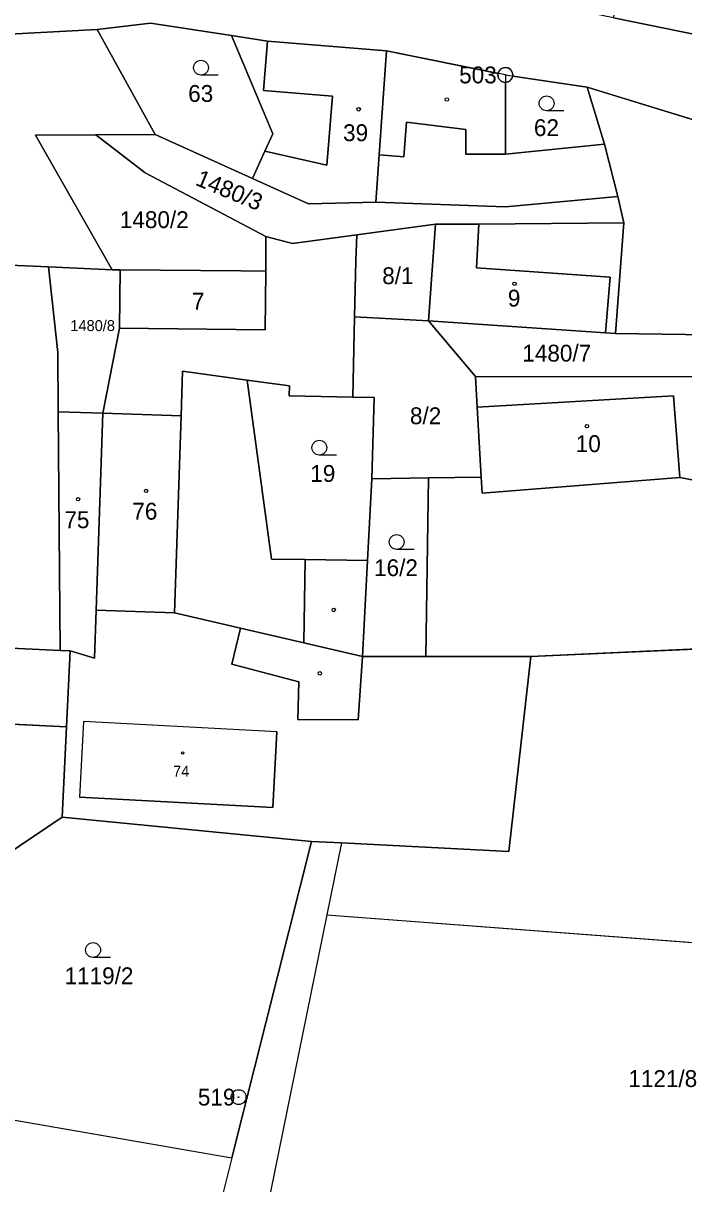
# Model space of a CAD drawing. Extents: x -760642 to -757221, y -1092371 to -1088855.
# Drawn here: x -759196.6 to -759130, y -1089899.5 to -1089782.4 of the extents above; entities that cross this region are included whole.
import ezdxf

# ---------------------------------------------------------------- set-up
doc = ezdxf.new("R2010")
doc.units = 0
for name, color, linetype in [('Vrstva 1', 7, 'Continuous'), ('Vrstva 17', 7, 'Continuous'), ('Vrstva 18', 7, 'Continuous'), ('Vrstva 19', 7, 'Continuous'), ('Vrstva 24', 7, 'Continuous'), ('Vrstva 25', 7, 'Continuous'), ('Vrstva 26', 7, 'Continuous'), ('Vrstva 27', 7, 'Continuous'), ('Vrstva 4', 7, 'Continuous')]:
    doc.layers.add(name, color=color, linetype=linetype)

msp = doc.modelspace()

# ---------------------------------------------------------------- linework, layer by layer
at = {"layer": 'Vrstva 1'}
for p, q in [((-759183.79, -1089782.45), (-759189.17, -1089783.09)), ((-759175.61, -1089783.69), (-759183.79, -1089782.45)), ((-759137.06, -1089781.89), (-759125.03, -1089784.34)), ((-759189.17, -1089783.09), (-759251.73, -1089786.4)), ((-759189.17, -1089783.09), (-759183.33, -1089793.67)), ((-759171.98, -1089784.24), (-759175.61, -1089783.69)), ((-759171.46, -1089793.61), (-759175.61, -1089783.69)), ((-759171.98, -1089784.24), (-759159.99, -1089785.24)), ((-759147.98, -1089787.66), (-759159.99, -1089785.24)), ((-759147.98, -1089787.66), (-759147.97, -1089795.66)), ((-759147.98, -1089787.66), (-759139.72, -1089788.89)), ((-759107.66, -1089798.75), (-759139.72, -1089788.89)), ((-759137.98, -1089794.63), (-759139.72, -1089788.89)), ((-759195.39, -1089793.75), (-759189.3, -1089793.71)), ((-759187.67, -1089807.31), (-759195.39, -1089793.75)), ((-759189.3, -1089793.71), (-759183.33, -1089793.67)), ((-759184.34, -1089797.55), (-759189.3, -1089793.71)), ((-759173.49, -1089798.11), (-759183.33, -1089793.67)), ((-759171.46, -1089793.61), (-759172.25, -1089795.35)), ((-759172.25, -1089795.35), (-759173.49, -1089798.11)), ((-759147.97, -1089795.66), (-759137.98, -1089794.63)), ((-759136.64, -1089799.91), (-759137.98, -1089794.63)), ((-759172.14, -1089803.96), (-759184.34, -1089797.55)), ((-759167.84, -1089800.66), (-759173.49, -1089798.11)), ((-759147.96, -1089800.96), (-759136.64, -1089799.91)), ((-759136.64, -1089799.91), (-759136.01, -1089802.59)), ((-759167.84, -1089800.66), (-759161.04, -1089800.5)), ((-759161.04, -1089800.5), (-759147.96, -1089800.96)), ((-759150.67, -1089802.72), (-759136.01, -1089802.59)), ((-759136.01, -1089802.59), (-759136.87, -1089813.75)), ((-759162.97, -1089803.79), (-759169.48, -1089804.68)), ((-759163.06, -1089806.39), (-759162.97, -1089803.79)), ((-759162.97, -1089803.79), (-759155.04, -1089802.71)), ((-759155.73, -1089812.48), (-759155.04, -1089802.71)), ((-759155.04, -1089802.71), (-759150.67, -1089802.72)), ((-759172.17, -1089807.46), (-759172.14, -1089803.96)), ((-759172.14, -1089803.96), (-759169.48, -1089804.68)), ((-759197.98, -1089806.87), (-759194.09, -1089807.03)), ((-759194.09, -1089807.03), (-759187.67, -1089807.31)), ((-759193.16, -1089815.67), (-759194.09, -1089807.03)), ((-759186.87, -1089807.32), (-759187.67, -1089807.31)), ((-759186.93, -1089813.22), (-759186.87, -1089807.32)), ((-759186.87, -1089807.32), (-759174.67, -1089807.44)), ((-759163.06, -1089806.39), (-759163.2, -1089812.06)), ((-759174.67, -1089807.44), (-759172.17, -1089807.46)), ((-759163.2, -1089812.06), (-759163.39, -1089820.18)), ((-759163.2, -1089812.06), (-759155.73, -1089812.48)), ((-759155.73, -1089812.48), (-759151, -1089818.09)), ((-759137.87, -1089813.68), (-759155.73, -1089812.48)), ((-759186.93, -1089813.22), (-759188.62, -1089821.79)), ((-759136.87, -1089813.75), (-759137.87, -1089813.68)), ((-759136.87, -1089813.75), (-759127.46, -1089813.87)), ((-759193.11, -1089821.64), (-759193.16, -1089815.67)), ((-759180.55, -1089817.55), (-759180.7, -1089822.05)), ((-759180.55, -1089817.55), (-759174.04, -1089818.45)), ((-759174.04, -1089818.45), (-759169.77, -1089819.04)), ((-759171.58, -1089836.5), (-759174.04, -1089818.45)), ((-759169.77, -1089819.04), (-759169.79, -1089820.05)), ((-759151, -1089818.09), (-759127.99, -1089818.13)), ((-759150.82, -1089821.19), (-759151, -1089818.09)), ((-759169.79, -1089820.05), (-759163.39, -1089820.18)), ((-759163.39, -1089820.18), (-759161.23, -1089820.22)), ((-759161.23, -1089820.22), (-759161.47, -1089828.41)), ((-759150.41, -1089828.24), (-759150.82, -1089821.19)), ((-759192.9, -1089845.73), (-759193.11, -1089821.64)), ((-759188.62, -1089821.79), (-759193.11, -1089821.64)), ((-759188.62, -1089821.79), (-759189.28, -1089841.67)), ((-759180.7, -1089822.05), (-759188.62, -1089821.79)), ((-759161.47, -1089828.41), (-759161.9, -1089836.65)), ((-759155.73, -1089828.32), (-759161.47, -1089828.41)), ((-759156, -1089846.35), (-759155.73, -1089828.32)), ((-759150.41, -1089828.24), (-759155.73, -1089828.32)), ((-759150.32, -1089829.84), (-759150.41, -1089828.24)), ((-759150.32, -1089829.84), (-759130.36, -1089828.26)), ((-759125.67, -1089829.2), (-759130.36, -1089828.26)), ((-759168.18, -1089836.55), (-759171.58, -1089836.5)), ((-759161.9, -1089836.65), (-759168.18, -1089836.55)), ((-759161.9, -1089836.65), (-759162.4, -1089846.35)), ((-759189.28, -1089841.67), (-759189.44, -1089846.51)), ((-759181.36, -1089841.93), (-759189.28, -1089841.67)), ((-759174.72, -1089843.48), (-759181.36, -1089841.93)), ((-759168.31, -1089844.97), (-759174.72, -1089843.48)), ((-759145.4, -1089846.35), (-759093.49, -1089843.95)), ((-759192.9, -1089845.73), (-759191.9, -1089845.78)), ((-759192.26, -1089853.42), (-759191.9, -1089845.78)), ((-759191.9, -1089845.78), (-759189.44, -1089846.51)), ((-759162.4, -1089846.35), (-759168.31, -1089844.97)), ((-759162.4, -1089846.35), (-759156, -1089846.35)), ((-759156, -1089846.35), (-759145.4, -1089846.35)), ((-759145.4, -1089846.35), (-759147.63, -1089866.02)), ((-759206.56, -1089852.74), (-759192.26, -1089853.42)), ((-759192.7, -1089862.53), (-759192.26, -1089853.42)), ((-759192.7, -1089862.53), (-759210.19, -1089874.31)), ((-759192.7, -1089862.53), (-759167.54, -1089864.99)), ((-759167.54, -1089864.99), (-759175.58, -1089896.9)), ((-759164.51, -1089865.15), (-759167.54, -1089864.99)), ((-759164.51, -1089865.15), (-759165.99, -1089872.4)), ((-759147.63, -1089866.02), (-759164.51, -1089865.15)), ((-759165.99, -1089872.4), (-759173.44, -1089908.9)), ((-759165.99, -1089872.4), (-759090.65, -1089878.08)), ((-759210.46, -1089890.87), (-759175.58, -1089896.9)), ((-759175.58, -1089896.9), (-759181.66, -1089921.05))]:
    msp.add_line(p, q, dxfattribs=at)
at = {"layer": 'Vrstva 24'}
for centre, radius in [((-759147.98, -1089787.66), 0.75), ((-759147.98, -1089787.66), 0.0327), ((-759174.91, -1089890.79), 0.75), ((-759174.91, -1089890.79), 0.0327)]:
    msp.add_circle(centre, radius, dxfattribs=at)
at = {"layer": 'Vrstva 25'}
for p, q in [((-759176.95, -1089787.68), (-759178.7, -1089787.68)), ((-759142.07, -1089791.28), (-759143.82, -1089791.28)), ((-759165.01, -1089826.02), (-759166.76, -1089826.02)), ((-759157.2, -1089835.53), (-759158.95, -1089835.53)), ((-759187.84, -1089876.7), (-759189.59, -1089876.7))]:
    msp.add_line(p, q, dxfattribs=at)
for centre, radius in [((-759178.7, -1089786.93), 0.75), ((-759143.82, -1089790.53), 0.75), ((-759162.78, -1089791.13), 0.175), ((-759153.89, -1089790.14), 0.175), ((-759147.06, -1089808.73), 0.175), ((-759139.75, -1089823.1), 0.175), ((-759166.76, -1089825.27), 0.75), ((-759184.24, -1089829.63), 0.175), ((-759191.1, -1089830.47), 0.175), ((-759158.95, -1089834.78), 0.75), ((-759165.3, -1089841.64), 0.175), ((-759166.7, -1089848.03), 0.175), ((-759180.55, -1089856.07), 0.117), ((-759189.59, -1089875.95), 0.75)]:
    msp.add_circle(centre, radius, dxfattribs=at)
at = {"layer": 'Vrstva 26'}
for points in [[(-759118.09, -1089757.67), (-759131.06, -1089758.08), (-759131.4, -1089747.57), (-759150.38, -1089748.18), (-759150.32, -1089753.17), (-759145.12, -1089753.12), (-759145.07, -1089757.83), (-759142.7, -1089757.82), (-759142.69, -1089760.22), (-759137.99, -1089760.2), (-759136.17, -1089771.28), (-759137.06, -1089781.89), (-759125.03, -1089784.34), (-759123.91, -1089784.65), (-759122.05, -1089777.39), (-759116.22, -1089778.89), (-759116.87, -1089757.63), (-759118.09, -1089757.67)], [(-759091.045, -1089805.166), (-759071.27, -1089811.68), (-759049.32, -1089817.46), (-759042.71, -1089818.15), (-759029.2, -1089819.24), (-759029.34, -1089815.45), (-759032.5, -1089809.35), (-759051.44, -1089805), (-759059.96, -1089803.05), (-759085.48, -1089798.88), (-759102.96, -1089790.95), (-759107.14, -1089789.05), (-759108.48, -1089788.44), (-759123.91, -1089784.65), (-759125.03, -1089784.34), (-759137.06, -1089781.89), (-759146.495, -1089779.96)], [(-759313.165, -1089810.283), (-759304.6, -1089803.62), (-759296.53, -1089798.79), (-759284.76, -1089793.72), (-759267.64, -1089788.76), (-759251.73, -1089786.4), (-759189.17, -1089783.09), (-759183.79, -1089782.45), (-759175.61, -1089783.69), (-759171.98, -1089784.24), (-759159.99, -1089785.24), (-759148.715, -1089787.512)], [(-759172.25, -1089795.35), (-759171.46, -1089793.61), (-759175.61, -1089783.69), (-759183.79, -1089782.45), (-759189.17, -1089783.09), (-759183.33, -1089793.67), (-759173.49, -1089798.11), (-759172.25, -1089795.35)], [(-759195.39, -1089793.75), (-759189.3, -1089793.71), (-759183.33, -1089793.67), (-759189.17, -1089783.09), (-759251.73, -1089786.4), (-759267.64, -1089788.76), (-759284.76, -1089793.72)], [(-759172.4, -1089789.22), (-759171.98, -1089784.24), (-759175.61, -1089783.69), (-759171.46, -1089793.61), (-759172.25, -1089795.35), (-759166, -1089796.78), (-759165.42, -1089789.81), (-759172.4, -1089789.22)], [(-759166, -1089796.78), (-759172.25, -1089795.35), (-759173.49, -1089798.11), (-759167.84, -1089800.66), (-759161.04, -1089800.5), (-759160.71, -1089795.73), (-759159.99, -1089785.24), (-759171.98, -1089784.24), (-759172.4, -1089789.22), (-759165.42, -1089789.81), (-759166, -1089796.78)], [(-759148.715, -1089787.512), (-759159.99, -1089785.24), (-759160.71, -1089795.73), (-759158.22, -1089795.91), (-759157.96, -1089792.42), (-759151.97, -1089793.17), (-759151.97, -1089795.66), (-759147.97, -1089795.66), (-759147.979, -1089788.41)], [(-759147.979, -1089788.41), (-759147.97, -1089795.66), (-759137.98, -1089794.63), (-759139.72, -1089788.89), (-759147.238, -1089787.77)], [(-759147.238, -1089787.77), (-759139.72, -1089788.89), (-759107.66, -1089798.75), (-759091.986, -1089804.829)], [(-759091.986, -1089804.829), (-759107.66, -1089798.75), (-759139.72, -1089788.89), (-759137.98, -1089794.63), (-759136.64, -1089799.91), (-759136.01, -1089802.59), (-759136.87, -1089813.75), (-759127.46, -1089813.87), (-759127.24, -1089813.87), (-759124.98, -1089801.03), (-759108.39, -1089804.66), (-759104.51, -1089813.82), (-759099.17, -1089811.94), (-759081.2, -1089811.04), (-759049.32, -1089817.46), (-759071.27, -1089811.68), (-759091.045, -1089805.166)], [(-759151.97, -1089795.66), (-759151.97, -1089793.17), (-759157.96, -1089792.42), (-759158.22, -1089795.91), (-759160.71, -1089795.73), (-759161.04, -1089800.5), (-759147.96, -1089800.96), (-759136.64, -1089799.91), (-759137.98, -1089794.63), (-759147.97, -1089795.66), (-759151.97, -1089795.66)], [(-759197.98, -1089806.87), (-759194.09, -1089807.03), (-759187.67, -1089807.31), (-759195.39, -1089793.75)], [(-759186.87, -1089807.32), (-759174.67, -1089807.44), (-759172.17, -1089807.46), (-759172.14, -1089803.96), (-759184.34, -1089797.55), (-759189.3, -1089793.71), (-759195.39, -1089793.75), (-759187.67, -1089807.31), (-759186.87, -1089807.32)], [(-759189.3, -1089793.71), (-759184.34, -1089797.55), (-759172.14, -1089803.96), (-759169.48, -1089804.68), (-759162.97, -1089803.79), (-759155.04, -1089802.71), (-759150.67, -1089802.72), (-759136.01, -1089802.59), (-759136.64, -1089799.91), (-759147.96, -1089800.96), (-759161.04, -1089800.5), (-759167.84, -1089800.66), (-759173.49, -1089798.11), (-759183.33, -1089793.67), (-759189.3, -1089793.71)], [(-759137.4, -1089808.08), (-759137.87, -1089813.68), (-759136.87, -1089813.75), (-759136.01, -1089802.59), (-759150.67, -1089802.72), (-759150.88, -1089807.11), (-759137.4, -1089808.08)], [(-759172.17, -1089807.46), (-759172.23, -1089813.37), (-759186.93, -1089813.22), (-759188.62, -1089821.79), (-759180.7, -1089822.05), (-759180.55, -1089817.55), (-759174.04, -1089818.45), (-759169.77, -1089819.04), (-759169.79, -1089820.05), (-759163.39, -1089820.18), (-759163.2, -1089812.06), (-759163.06, -1089806.39), (-759162.97, -1089803.79), (-759169.48, -1089804.68), (-759172.14, -1089803.96), (-759172.17, -1089807.46)], [(-759155.04, -1089802.71), (-759162.97, -1089803.79), (-759163.06, -1089806.39), (-759163.2, -1089812.06), (-759155.73, -1089812.48), (-759155.04, -1089802.71)], [(-759137.4, -1089808.08), (-759150.88, -1089807.11), (-759150.67, -1089802.72), (-759155.04, -1089802.71), (-759155.73, -1089812.48), (-759137.87, -1089813.68), (-759137.4, -1089808.08)], [(-759198.34, -1089806.85), (-759198.58, -1089814.41), (-759214.17, -1089813.83), (-759214.93, -1089832.99), (-759211.28, -1089833.14), (-759211.34, -1089844.86), (-759192.9, -1089845.73), (-759193.11, -1089821.64), (-759193.16, -1089815.67), (-759194.09, -1089807.03), (-759197.98, -1089806.87), (-759198.34, -1089806.85)], [(-759186.87, -1089807.32), (-759187.67, -1089807.31), (-759194.09, -1089807.03), (-759193.16, -1089815.67), (-759193.11, -1089821.64), (-759188.62, -1089821.79), (-759186.93, -1089813.22), (-759186.87, -1089807.32)], [(-759172.23, -1089813.37), (-759172.17, -1089807.46), (-759174.67, -1089807.44), (-759186.87, -1089807.32), (-759186.93, -1089813.22), (-759172.23, -1089813.37)], [(-759155.73, -1089812.48), (-759163.2, -1089812.06), (-759163.39, -1089820.18), (-759161.23, -1089820.22), (-759161.47, -1089828.41), (-759155.73, -1089828.32), (-759150.41, -1089828.24), (-759150.82, -1089821.19), (-759151, -1089818.09), (-759155.73, -1089812.48)], [(-759151, -1089818.09), (-759127.99, -1089818.13), (-759127.24, -1089813.87), (-759127.46, -1089813.87), (-759136.87, -1089813.75), (-759137.87, -1089813.68), (-759155.73, -1089812.48), (-759151, -1089818.09)], [(-759168.31, -1089844.97), (-759168.18, -1089836.55), (-759171.58, -1089836.5), (-759174.04, -1089818.45), (-759180.55, -1089817.55), (-759180.7, -1089822.05), (-759181.36, -1089841.93), (-759174.72, -1089843.48), (-759168.31, -1089844.97)], [(-759168.18, -1089836.55), (-759161.9, -1089836.65), (-759161.47, -1089828.41), (-759161.23, -1089820.22), (-759163.39, -1089820.18), (-759169.79, -1089820.05), (-759169.77, -1089819.04), (-759174.04, -1089818.45), (-759171.58, -1089836.5), (-759168.18, -1089836.55)], [(-759131.01, -1089820.04), (-759130.36, -1089828.26), (-759125.67, -1089829.2), (-759119.77, -1089828.99), (-759119.79, -1089820.53), (-759125.66, -1089818.71), (-759127.99, -1089818.13), (-759151, -1089818.09), (-759150.82, -1089821.19), (-759131.01, -1089820.04)], [(-759150.82, -1089821.19), (-759150.41, -1089828.24), (-759150.32, -1089829.84), (-759130.36, -1089828.26), (-759131.01, -1089820.04), (-759150.82, -1089821.19)], [(-759189.44, -1089846.51), (-759189.28, -1089841.67), (-759188.62, -1089821.79), (-759193.11, -1089821.64), (-759192.9, -1089845.73), (-759191.9, -1089845.78), (-759189.44, -1089846.51)], [(-759188.62, -1089821.79), (-759189.28, -1089841.67), (-759181.36, -1089841.93), (-759180.7, -1089822.05), (-759188.62, -1089821.79)], [(-759156, -1089846.35), (-759155.73, -1089828.32), (-759161.47, -1089828.41), (-759161.9, -1089836.65), (-759162.4, -1089846.35), (-759156, -1089846.35)], [(-759111.03, -1089828.68), (-759119.77, -1089828.99), (-759125.67, -1089829.2), (-759130.36, -1089828.26), (-759150.32, -1089829.84), (-759150.41, -1089828.24), (-759155.73, -1089828.32), (-759156, -1089846.35), (-759145.4, -1089846.35), (-759093.49, -1089843.95), (-759096.14, -1089828.16), (-759111.03, -1089828.68)], [(-759168.31, -1089844.97), (-759162.4, -1089846.35), (-759161.9, -1089836.65), (-759168.18, -1089836.55), (-759168.31, -1089844.97)], [(-759191.9, -1089845.78), (-759192.26, -1089853.42), (-759192.7, -1089862.53), (-759167.54, -1089864.99), (-759164.51, -1089865.15), (-759147.63, -1089866.02), (-759145.4, -1089846.35), (-759156, -1089846.35), (-759162.4, -1089846.35), (-759162.84, -1089852.71), (-759168.92, -1089852.68), (-759168.82, -1089848.88), (-759175.57, -1089847.1), (-759174.72, -1089843.48), (-759181.36, -1089841.93), (-759189.28, -1089841.67), (-759189.44, -1089846.51), (-759191.9, -1089845.78)], [(-759174.72, -1089843.48), (-759175.57, -1089847.1), (-759168.82, -1089848.88), (-759168.92, -1089852.68), (-759162.84, -1089852.71), (-759162.4, -1089846.35), (-759168.31, -1089844.97), (-759174.72, -1089843.48)], [(-759211.34, -1089844.86), (-759215.04, -1089844.69), (-759215.71, -1089852.31), (-759208.57, -1089852.65), (-759206.56, -1089852.74), (-759192.26, -1089853.42), (-759191.9, -1089845.78), (-759192.9, -1089845.73), (-759211.34, -1089844.86)], [(-759093.49, -1089843.95), (-759145.4, -1089846.35), (-759147.63, -1089866.02), (-759164.51, -1089865.15), (-759165.99, -1089872.4), (-759090.65, -1089878.08), (-759093.49, -1089843.95)], [(-759192.7, -1089862.53), (-759192.26, -1089853.42), (-759206.56, -1089852.74), (-759208.57, -1089852.65), (-759209, -1089858.46), (-759209.83, -1089870.65), (-759210.19, -1089874.31), (-759192.7, -1089862.53)], [(-759171.04, -1089853.93), (-759190.57, -1089852.89), (-759190.97, -1089860.53), (-759171.45, -1089861.57), (-759171.04, -1089853.93)], [(-759167.54, -1089864.99), (-759192.7, -1089862.53), (-759210.19, -1089874.31), (-759211.05, -1089885.12), (-759209.61, -1089885.8), (-759210.46, -1089890.87), (-759175.58, -1089896.9), (-759167.54, -1089864.99)]]:
    msp.add_lwpolyline(points, dxfattribs=at)
for start, end in [(0, 168.60752), (168.60752, 180), (180, 270.07162), (270.07162, 351.5303), (351.5303, 0)]:
    msp.add_arc((-759147.98, -1089787.66), 0.75, start, end, dxfattribs=at)
at = {"layer": 'Vrstva 27'}
msp.add_lwpolyline([(-759286.99, -1089870.84), (-759236.1, -1089885.41), (-759233.14, -1089867.25), (-759234.41, -1089885.19), (-759230.7, -1089885.5), (-759232.25, -1089895.53), (-759236.58, -1089920.99), (-759238.06, -1089945.94), (-759228.14, -1089947.36), (-759222.04, -1089926.62), (-759214.17, -1089898.33), (-759211.23, -1089887.35), (-759211.05, -1089885.12), (-759209.61, -1089885.8), (-759210.46, -1089890.87), (-759175.58, -1089896.9), (-759167.54, -1089864.99), (-759164.51, -1089865.15), (-759165.99, -1089872.4), (-759090.65, -1089878.08)], dxfattribs=at)
at = {"layer": 'Vrstva 4'}
for p, q in [((-759172.4, -1089789.22), (-759171.98, -1089784.24)), ((-759159.99, -1089785.24), (-759160.71, -1089795.73)), ((-759165.42, -1089789.81), (-759172.4, -1089789.22)), ((-759166, -1089796.78), (-759165.42, -1089789.81)), ((-759157.96, -1089792.42), (-759158.22, -1089795.91)), ((-759151.97, -1089793.17), (-759157.96, -1089792.42)), ((-759151.97, -1089793.17), (-759151.97, -1089795.66)), ((-759166, -1089796.78), (-759172.25, -1089795.35)), ((-759160.71, -1089795.73), (-759161.04, -1089800.5)), ((-759160.71, -1089795.73), (-759158.22, -1089795.91)), ((-759151.97, -1089795.66), (-759147.97, -1089795.66)), ((-759150.67, -1089802.72), (-759150.88, -1089807.11)), ((-759150.88, -1089807.11), (-759137.4, -1089808.08)), ((-759172.23, -1089813.37), (-759172.17, -1089807.46)), ((-759137.4, -1089808.08), (-759137.87, -1089813.68)), ((-759172.23, -1089813.37), (-759186.93, -1089813.22)), ((-759150.82, -1089821.19), (-759131.01, -1089820.04)), ((-759131.01, -1089820.04), (-759130.36, -1089828.26)), ((-759180.7, -1089822.05), (-759181.36, -1089841.93)), ((-759168.18, -1089836.55), (-759168.31, -1089844.97)), ((-759175.57, -1089847.1), (-759174.72, -1089843.48)), ((-759211.34, -1089844.86), (-759192.9, -1089845.73)), ((-759175.57, -1089847.1), (-759168.82, -1089848.88)), ((-759162.4, -1089846.35), (-759162.84, -1089852.71)), ((-759168.82, -1089848.88), (-759168.92, -1089852.68)), ((-759190.57, -1089852.89), (-759190.97, -1089860.53)), ((-759171.04, -1089853.93), (-759190.57, -1089852.89)), ((-759168.92, -1089852.68), (-759162.84, -1089852.71)), ((-759171.04, -1089853.93), (-759171.45, -1089861.57)), ((-759171.45, -1089861.57), (-759190.97, -1089860.53))]:
    msp.add_line(p, q, dxfattribs=at)

# ---------------------------------------------------------------- texts
at = {"layer": 'Vrstva 17'}
for s, p in [('503', (-759152.646, -1089788.51)), ('519', (-759179.014, -1089891.64))]:
    msp.add_text(s, height=1.7, dxfattribs=at).set_placement(p)
at = {"layer": 'Vrstva 18'}
for s, height, p in [('63', 1.7, (-759179.99, -1089790.38)), ('62', 1.7, (-759145.1, -1089793.83)), ('1480/2', 1.7, (-759186.89, -1089803.11)), ('1480/8', 1.1, (-759191.882, -1089813.5)), ('1480/7', 1.7, (-759146.27, -1089816.58)), ('19', 1.7, (-759167.67, -1089828.72)), ('16/2', 1.7, (-759161.23, -1089838.23)), ('1119/2', 1.7, (-759192.471, -1089879.4)), ('1121/8', 1.7, (-759135.57, -1089889.77))]:
    msp.add_text(s, height=height, dxfattribs=at).set_placement(p)
msp.add_text('1480/3', height=1.7, rotation=337.4127, dxfattribs=at).set_placement((-759179.36, -1089798.73))
at = {"layer": 'Vrstva 19'}
for s, height, p in [('39', 1.7, (-759164.36, -1089794.34)), ('8/1', 1.7, (-759160.41, -1089808.77)), ('7', 1.7, (-759179.61, -1089811.33)), ('9', 1.7, (-759147.73, -1089811.03)), ('8/2', 1.7, (-759157.61, -1089822.9)), ('10', 1.7, (-759140.88, -1089825.71)), ('75', 1.7, (-759192.482, -1089833.39)), ('76', 1.7, (-759185.63, -1089832.53)), ('74', 1.1, (-759181.514, -1089858.46))]:
    msp.add_text(s, height=height, dxfattribs=at).set_placement(p)

doc.saveas('drawing.dxf')
